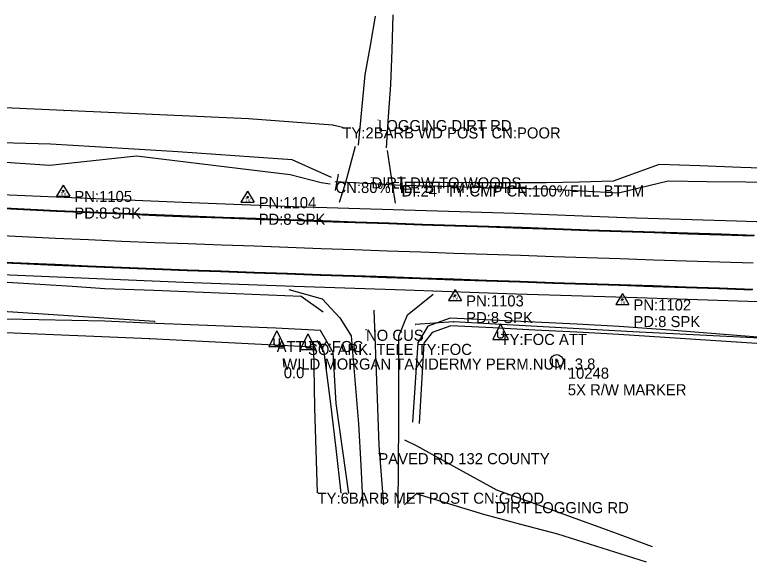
# Model space of a CAD drawing. Extents: x 878399 to 889864, y 1564003 to 1567413.
# Drawn here: x 887107.2 to 887438.5, y 1564312.3 to 1564559.3 of the extents above; entities that cross this region are included whole.
import ezdxf

# ---------------------------------------------------------------- set-up
doc = ezdxf.new("R2010")
doc.units = 0
for name, color, linetype in [('S_DITCHLINE', 7, 'Continuous'), ('S_DRG_PT_SYM', 7, 'Continuous'), ('S_DRIVEWAY', 7, 'Continuous'), ('S_EDGE_PAVEMENT', 7, 'Continuous'), ('S_FENCE', 7, 'Continuous'), ('S_FENCE_ANNOT', 7, 'Continuous'), ('S_FIBER_OPTIC_CABLE', 7, 'Continuous'), ('S_HEADWALL', 7, 'Continuous'), ('S_IRON_PIN', 7, 'Continuous'), ('S_IRON_PIN_ANNOT', 7, 'Continuous'), ('S_MSC_PT_SYM', 7, 'Continuous'), ('S_PAVEMENT_CROWN', 7, 'Continuous'), ('S_SECONDARY_CTL', 7, 'Continuous'), ('S_SECONDARY_CTL_ANNOT', 7, 'Continuous'), ('S_SHOULDER', 7, 'Continuous'), ('S_SIDE_DRAIN', 7, 'Continuous'), ('S_SIDE_DRAIN_ANNOT', 7, 'Continuous'), ('S_SIGN', 7, 'Continuous'), ('S_SIGN_ANNOT', 7, 'Continuous'), ('S_SURVEY_TEXT_ANNOT', 7, 'Continuous'), ('S_TRAILS', 7, 'Continuous'), ('S_UTILITY_POLE', 7, 'Continuous'), ('S_UTILITY_POLE_ANNOT', 7, 'Continuous'), ('S_UTL_PT_SYM', 7, 'Continuous')]:
    doc.layers.add(name, color=color, linetype=linetype)

msp = doc.modelspace()

# ---------------------------------------------------------------- linework, layer by layer
at = {"layer": 'S_DITCHLINE'}
for points in [[(887250.01, 1564485.81), (887245.73, 1564487.85), (887232.27, 1564493.81), (887215.08, 1564494.99), (887197.9, 1564496.18), (887180.71, 1564497.37), (887163.52, 1564498.56), (887143.39, 1564499.75), (887123.26, 1564500.95), (887100.99, 1564501.53), (887078.71, 1564502.11), (887056.44, 1564502.7), (887034.17, 1564503.28), (887025.82, 1564506), (887012.29, 1564506.57), (886998.76, 1564507.13), (886985.23, 1564507.7), (886971.7, 1564508.27), (886951.72, 1564511), (886939.09, 1564511.66), (886934.32, 1564513.76), (886930.08, 1564521.74), (886921.5, 1564529.82)], [(887249.48, 1564482.84), (887245.32, 1564483.43), (887231.36, 1564487.02), (887214.02, 1564489.13), (887196.69, 1564491.24), (887179.36, 1564493.35), (887162.02, 1564495.47), (887142.5, 1564493.34), (887122.97, 1564491.22), (887100.76, 1564492.83), (887078.55, 1564494.43), (887056.34, 1564496.04), (887034.13, 1564497.65), (887018.27, 1564499.44), (887002.4, 1564501.24), (886986.53, 1564503.03), (886970.67, 1564504.83), (886951.34, 1564504.75), (886940.46, 1564504.61), (886937.16, 1564502.38), (886934.26, 1564496.23)], [(887453.1, 1564489.78), (887434.65, 1564490.42), (887416.2, 1564491.05), (887397.75, 1564491.69), (887377.12, 1564484.24), (887361.95, 1564483.82), (887346.78, 1564483.41), (887330.86, 1564483.46), (887314.93, 1564483.51), (887299, 1564483.57), (887283.07, 1564483.62)], [(887454.31, 1564483.52), (887436.85, 1564483.75), (887419.4, 1564483.97), (887401.94, 1564484.19), (887379.4, 1564478.72), (887363.07, 1564479.63), (887346.74, 1564480.55), (887330.76, 1564480.96), (887314.77, 1564481.37), (887298.78, 1564481.79), (887282.79, 1564482.2)], [(887257.8, 1564343.38), (887254.99, 1564363.66), (887252.17, 1564383.94), (887250.75, 1564406.9), (887245.07, 1564416.93), (887224.89, 1564417.88), (887205.62, 1564418.66), (887186.36, 1564419.45), (887167.1, 1564420.23), (887147.83, 1564421.01), (887132.93, 1564421.35), (887118.03, 1564421.7), (887103.12, 1564422.04), (887088.22, 1564422.38), (887066.16, 1564423.4), (887044.11, 1564424.42), (887022.06, 1564425.44), (887000, 1564426.46), (886983.96, 1564429.17), (886968.92, 1564431.25), (886953.89, 1564433.34), (886937.25, 1564432.42), (886929.06, 1564437.68), (886932.3, 1564446.5)], [(887442.27, 1564413.89), (887421.45, 1564415.51), (887400.62, 1564417.12), (887379.8, 1564418.74), (887360.74, 1564419.67), (887341.68, 1564420.6), (887322.62, 1564421.53), (887303.56, 1564422.46), (887293.42, 1564418.88), (887288.97, 1564411.32), (887287.77, 1564393.41), (887286.57, 1564375.5)], [(887441.87, 1564411.02), (887421.14, 1564412.39), (887400.4, 1564413.76), (887379.67, 1564415.13), (887360.72, 1564416.1), (887341.77, 1564417.08), (887322.82, 1564418.05), (887303.87, 1564419.02), (887295.37, 1564416), (887291.62, 1564411.11), (887290.63, 1564393.01), (887289.64, 1564374.92)], [(887254.42, 1564343.43), (887252.11, 1564363.6), (887249.8, 1564383.77), (887246.75, 1564407.12), (887243.59, 1564412.39)]]:
    msp.add_lwpolyline(points, dxfattribs=at)
at = {"layer": 'S_DRG_PT_SYM'}
for points in [[(887251.84, 1564483.86), (887251.84, 1564483.91), (887251.84, 1564483.86), (887251.79, 1564483.86), (887251.84, 1564483.86), (887251.84, 1564483.81), (887251.84, 1564483.86), (887251.89, 1564483.86)], [(887281.64, 1564482.29), (887281.64, 1564482.34), (887281.64, 1564482.29), (887281.59, 1564482.29), (887281.64, 1564482.29), (887281.64, 1564482.24), (887281.64, 1564482.29), (887281.69, 1564482.29)]]:
    msp.add_lwpolyline(points, dxfattribs=at)
at = {"layer": 'S_DRIVEWAY'}
for points in [[(887253.63, 1564474.8), (887256.38, 1564483.18), (887260.84, 1564500)], [(887275.19, 1564498), (887277.41, 1564483.04), (887278.79, 1564474.31)]]:
    msp.add_lwpolyline(points, dxfattribs=at)
at = {"layer": 'S_EDGE_PAVEMENT'}
for points in [[(887096.19, 1564472.17), (887111.17, 1564471.44), (887125.93, 1564470.72), (887125.93, 1564470.72), (887125.93, 1564470.72), (887140.91, 1564470.04), (887155.89, 1564469.42), (887170.87, 1564468.79), (887185.85, 1564468.18), (887200.84, 1564467.65), (887215.82, 1564467.12), (887230.81, 1564466.59), (887245.79, 1564466.07), (887260.77, 1564465.56), (887275.76, 1564465.05), (887290.75, 1564464.55), (887305.73, 1564464.06), (887320.72, 1564463.57), (887335.7, 1564463.07), (887350.68, 1564462.53), (887365.65, 1564461.99), (887380.63, 1564461.45), (887395.62, 1564460.99), (887410.61, 1564460.53), (887425.59, 1564460.07), (887440.58, 1564459.57)], [(887096.49, 1564472.5), (887111.46, 1564471.77), (887126.23, 1564471.05), (887126.23, 1564471.05), (887126.23, 1564471.05), (887141.21, 1564470.38), (887156.18, 1564469.75), (887171.16, 1564469.12), (887186.15, 1564468.51), (887201.13, 1564467.98), (887216.11, 1564467.45), (887231.1, 1564466.92), (887246.08, 1564466.41), (887261.06, 1564465.9), (887276.05, 1564465.38), (887291.03, 1564464.88), (887306.02, 1564464.39), (887321, 1564463.9), (887335.98, 1564463.4), (887350.97, 1564462.86), (887365.93, 1564462.33), (887380.91, 1564461.79), (887395.9, 1564461.32), (887410.89, 1564460.86), (887425.87, 1564460.41), (887440.86, 1564459.9)], [(887094.8, 1564447.72), (887109.78, 1564447.06), (887125.06, 1564446.4), (887140.04, 1564445.76), (887155.02, 1564445.15), (887170, 1564444.53), (887184.98, 1564443.93), (887199.96, 1564443.4), (887214.95, 1564442.87), (887229.93, 1564442.35), (887244.92, 1564441.83), (887259.9, 1564441.33), (887274.89, 1564440.82), (887289.88, 1564440.3), (887304.86, 1564439.78), (887319.84, 1564439.26), (887334.83, 1564438.74), (887334.83, 1564438.74), (887349.81, 1564438.25), (887364.82, 1564437.76), (887379.81, 1564437.27), (887394.79, 1564436.76), (887409.78, 1564436.24), (887424.76, 1564435.73), (887439.75, 1564435.22)], [(887095.09, 1564448.05), (887110.08, 1564447.4), (887125.35, 1564446.73), (887140.33, 1564446.09), (887155.31, 1564445.48), (887170.29, 1564444.87), (887185.27, 1564444.26), (887200.26, 1564443.74), (887215.24, 1564443.21), (887230.22, 1564442.68), (887245.21, 1564442.17), (887260.19, 1564441.66), (887275.18, 1564441.15), (887290.16, 1564440.64), (887305.15, 1564440.11), (887320.13, 1564439.59), (887335.11, 1564439.07), (887335.11, 1564439.07), (887350.1, 1564438.58), (887365.11, 1564438.09), (887380.09, 1564437.61), (887395.07, 1564437.1), (887410.06, 1564436.58), (887425.04, 1564436.06), (887440.03, 1564435.55)], [(887230.77, 1564435.39), (887245.83, 1564431.09), (887253.86, 1564422.63), (887258.88, 1564414.4), (887260.57, 1564394.56), (887262.25, 1564374.72), (887263.24, 1564356.07), (887264.22, 1564337.43)], [(887230.77, 1564435.39), (887245.83, 1564431.09), (887253.86, 1564422.63), (887258.88, 1564414.4), (887260.57, 1564394.56), (887262.25, 1564374.72), (887263.24, 1564356.07), (887264.22, 1564337.43)], [(887280.03, 1564336.91), (887280.19, 1564356.21), (887280.35, 1564375.52), (887280.41, 1564394.91), (887280.46, 1564414.31), (887284.37, 1564423.97), (887295.84, 1564433.31)], [(887280.03, 1564336.91), (887280.19, 1564356.21), (887280.35, 1564375.52), (887280.41, 1564394.91), (887280.46, 1564414.31), (887284.37, 1564423.97), (887295.84, 1564433.31)]]:
    msp.add_lwpolyline(points, dxfattribs=at)
at = {"layer": 'S_FENCE'}
for p, q in [((887129.36, 1564516.14), (887041.56, 1564519.77)), ((887212.6, 1564512.39), (887129.36, 1564516.14)), ((887250.71, 1564509.45), (887212.6, 1564512.39)), ((887254.95, 1564508.47), (887250.71, 1564509.45)), ((887168.04, 1564413.11), (887041.64, 1564418.49)), ((887242.08, 1564409.4), (887168.04, 1564413.11)), ((887242.48, 1564382), (887242.08, 1564409.4)), ((887243.76, 1564343.74), (887242.48, 1564382))]:
    msp.add_line(p, q, dxfattribs=at)
at = {"layer": 'S_FIBER_OPTIC_CABLE'}
for p, q in [((887170.15, 1564420.88), (887088.63, 1564426.34)), ((887304.99, 1564420.78), (887287.85, 1564419.57)), ((887385.92, 1564416.28), (887304.99, 1564420.78)), ((887488.84, 1564411.08), (887385.92, 1564416.28))]:
    msp.add_line(p, q, dxfattribs=at)
at = {"layer": 'S_HEADWALL'}
for points in [[(887251.9, 1564479.95), (887253.17, 1564487.35)], [(887286.41, 1564480.41), (887281.29, 1564480.58), (887281.42, 1564486.25)]]:
    msp.add_lwpolyline(points, dxfattribs=at)
at = {"layer": 'S_IRON_PIN'}
for radius in [2.91, 0.411, 0.262, 0.212, 0.145, 0.0822, 0.0581]:
    msp.add_circle((887351.63, 1564403.12), radius, dxfattribs=at)
at = {"layer": 'S_MSC_PT_SYM'}
for points in [[(887129.36, 1564516.14), (887129.36, 1564516.19), (887129.36, 1564516.14), (887129.31, 1564516.14), (887129.36, 1564516.14), (887129.36, 1564516.09), (887129.36, 1564516.14), (887129.41, 1564516.14)], [(887212.6, 1564512.39), (887212.6, 1564512.44), (887212.6, 1564512.39), (887212.55, 1564512.39), (887212.6, 1564512.39), (887212.6, 1564512.34), (887212.6, 1564512.39), (887212.65, 1564512.39)], [(887250.71, 1564509.45), (887250.71, 1564509.5), (887250.71, 1564509.45), (887250.66, 1564509.45), (887250.71, 1564509.45), (887250.71, 1564509.4), (887250.71, 1564509.45), (887250.76, 1564509.45)], [(887271.07, 1564511.77), (887271.07, 1564511.82), (887271.07, 1564511.77), (887271.02, 1564511.77), (887271.07, 1564511.77), (887271.07, 1564511.72), (887271.07, 1564511.77), (887271.12, 1564511.77)], [(887254.95, 1564508.47), (887254.95, 1564508.52), (887254.95, 1564508.47), (887254.9, 1564508.47), (887254.95, 1564508.47), (887254.95, 1564508.42), (887254.95, 1564508.47), (887255, 1564508.47)], [(887268.08, 1564485.92), (887268.08, 1564485.97), (887268.08, 1564485.92), (887268.03, 1564485.92), (887268.08, 1564485.92), (887268.08, 1564485.87), (887268.08, 1564485.92), (887268.13, 1564485.92)], [(887265.6, 1564417.2), (887265.6, 1564417.25), (887265.6, 1564417.2), (887265.55, 1564417.2), (887265.6, 1564417.2), (887265.6, 1564417.15), (887265.6, 1564417.2), (887265.65, 1564417.2)], [(887168.04, 1564413.11), (887168.04, 1564413.16), (887168.04, 1564413.11), (887167.99, 1564413.11), (887168.04, 1564413.11), (887168.04, 1564413.06), (887168.04, 1564413.11), (887168.09, 1564413.11)], [(887242.08, 1564409.4), (887242.08, 1564409.45), (887242.08, 1564409.4), (887242.03, 1564409.4), (887242.08, 1564409.4), (887242.08, 1564409.35), (887242.08, 1564409.4), (887242.13, 1564409.4)], [(887228.26, 1564404.23), (887228.26, 1564404.28), (887228.26, 1564404.23), (887228.21, 1564404.23), (887228.26, 1564404.23), (887228.26, 1564404.18), (887228.26, 1564404.23), (887228.31, 1564404.23)], [(887228.52, 1564400.33), (887228.52, 1564400.38), (887228.52, 1564400.33), (887228.47, 1564400.33), (887228.52, 1564400.33), (887228.52, 1564400.28), (887228.52, 1564400.33), (887228.57, 1564400.33)], [(887242.48, 1564382), (887242.48, 1564382.05), (887242.48, 1564382), (887242.43, 1564382), (887242.48, 1564382), (887242.48, 1564381.95), (887242.48, 1564382), (887242.53, 1564382)], [(887271.16, 1564361.56), (887271.16, 1564361.61), (887271.16, 1564361.56), (887271.11, 1564361.56), (887271.16, 1564361.56), (887271.16, 1564361.51), (887271.16, 1564361.56), (887271.21, 1564361.56)], [(887243.76, 1564343.74), (887243.76, 1564343.79), (887243.76, 1564343.74), (887243.71, 1564343.74), (887243.76, 1564343.74), (887243.76, 1564343.69), (887243.76, 1564343.74), (887243.81, 1564343.74)], [(887323.94, 1564339.46), (887323.94, 1564339.51), (887323.94, 1564339.46), (887323.89, 1564339.46), (887323.94, 1564339.46), (887323.94, 1564339.41), (887323.94, 1564339.46), (887323.99, 1564339.46)]]:
    msp.add_lwpolyline(points, dxfattribs=at)
at = {"layer": 'S_PAVEMENT_CROWN'}
for points in [[(887095.49, 1564459.96), (887110.47, 1564459.21), (887125.49, 1564458.49), (887140.47, 1564457.85), (887155.44, 1564457.21), (887170.43, 1564456.56), (887185.41, 1564456.03), (887200.39, 1564455.5), (887215.38, 1564454.97), (887230.36, 1564454.44), (887245.35, 1564453.9), (887260.33, 1564453.37), (887275.32, 1564452.84), (887290.3, 1564452.32), (887305.28, 1564451.81), (887320.27, 1564451.29), (887335.25, 1564450.79), (887350.24, 1564450.29), (887365.23, 1564449.78), (887380.21, 1564449.29), (887395.2, 1564448.8), (887410.18, 1564448.31), (887425.17, 1564447.82), (887440.15, 1564447.32)], [(887269.17, 1564426.01), (887269.9, 1564406.12), (887270.63, 1564386.23), (887271.46, 1564365.01), (887272.49, 1564351.66), (887273.52, 1564338.31)]]:
    msp.add_lwpolyline(points, dxfattribs=at)
at = {"layer": 'S_SECONDARY_CTL'}
for p, q in [((887129.07, 1564482.42), (887126.06, 1564477.47)), ((887129.07, 1564482.42), (887132.02, 1564477.47)), ((887212.17, 1564479.64), (887209.16, 1564474.69)), ((887212.17, 1564479.64), (887215.12, 1564474.69)), ((887126.06, 1564477.47), (887132.02, 1564477.47)), ((887209.16, 1564474.69), (887215.12, 1564474.69)), ((887305.75, 1564435.32), (887302.74, 1564430.37)), ((887305.75, 1564435.32), (887308.7, 1564430.37)), ((887381.22, 1564433.5), (887378.21, 1564428.54)), ((887381.22, 1564433.5), (887384.17, 1564428.54)), ((887302.74, 1564430.37), (887308.7, 1564430.37)), ((887378.21, 1564428.54), (887384.17, 1564428.54))]:
    msp.add_line(p, q, dxfattribs=at)
for centre, radius in [((887129.07, 1564479.81), 0.311), ((887129.07, 1564479.81), 0.183), ((887129.07, 1564479.81), 0.103), ((887212.17, 1564477.03), 0.311), ((887212.17, 1564477.03), 0.183), ((887212.17, 1564477.03), 0.103), ((887305.75, 1564432.71), 0.311), ((887305.75, 1564432.71), 0.183), ((887305.75, 1564432.71), 0.103), ((887381.22, 1564430.89), 0.311), ((887381.22, 1564430.89), 0.183), ((887381.22, 1564430.89), 0.103)]:
    msp.add_circle(centre, radius, dxfattribs=at)
at = {"layer": 'S_SHOULDER'}
for points in [[(886439.19, 1564543.9), (886488.35, 1564534.77), (886536.94, 1564526.51), (886586.36, 1564518.81), (886635.93, 1564512.26), (886685.62, 1564506.57), (886734.54, 1564501.74), (886784.34, 1564497.16), (886834.2, 1564493.36), (886883.7, 1564489.95), (886933.63, 1564487.46), (886983.53, 1564484.37), (887033.43, 1564481.47), (887083.36, 1564478.88), (887132.96, 1564476.84), (887182.9, 1564474.75), (887232.84, 1564472.73), (887282.79, 1564471.29), (887332.75, 1564469.72), (887382.66, 1564467.88), (887432.62, 1564466.36), (887482.58, 1564464.72)], [(886434.5, 1564507.62), (886483.69, 1564498.68), (886533.94, 1564490.3), (886583.39, 1564482.88), (886632.96, 1564476.31), (886682.65, 1564470.63), (886733.41, 1564465.04), (886783.26, 1564461.07), (886833.15, 1564457.67), (886883.53, 1564454.57), (886933.43, 1564451.65), (886983.34, 1564448.74), (887033.23, 1564445.65), (887083.15, 1564442.94), (887133.5, 1564440.74), (887183.43, 1564438.72), (887233.38, 1564436.89), (887283.33, 1564435.19), (887333.28, 1564433.45), (887383.27, 1564431.95), (887433.22, 1564430.22), (887483.18, 1564428.56)], [(887246.33, 1564425.09), (887236.36, 1564432.21), (887214.23, 1564433.08), (887192.1, 1564433.96), (887169.96, 1564434.84), (887147.83, 1564435.71), (887133.15, 1564436.63), (887118.47, 1564437.56), (887103.79, 1564438.48)]]:
    msp.add_lwpolyline(points, dxfattribs=at)
at = {"layer": 'S_SIDE_DRAIN'}
msp.add_line((887281.64, 1564482.29), (887251.84, 1564483.86), dxfattribs=at)
at = {"layer": 'S_SIGN'}
msp.add_line((887228.26, 1564404.23), (887228.52, 1564400.33), dxfattribs=at)
at = {"layer": 'S_TRAILS'}
for points in [[(887277.75, 1564559.28), (887277.2, 1564543.48), (887276.66, 1564527.67), (887275.66, 1564513.44), (887274.67, 1564499.21)], [(887269.8, 1564558.66), (887267.44, 1564545.39), (887265.08, 1564532.12), (887263.6, 1564516.31), (887262.11, 1564500.51)], [(887282.97, 1564367.56), (887288.48, 1564364.92), (887306.43, 1564354.97), (887324.38, 1564345.02), (887340.42, 1564339.24), (887356.47, 1564333.45), (887375.59, 1564326.47), (887394.71, 1564319.49)], [(887392.1, 1564312.32), (887372.12, 1564318.67), (887352.13, 1564325.02), (887335.46, 1564329.43), (887318.78, 1564333.84), (887303.47, 1564338.51), (887288.17, 1564343.18), (887282.94, 1564338.31)]]:
    msp.add_lwpolyline(points, dxfattribs=at)
at = {"layer": 'S_UTILITY_POLE'}
for p, q in [((887326.26, 1564419.86), (887322.73, 1564412.77)), ((887326.26, 1564419.86), (887329.74, 1564412.77)), ((887225.32, 1564416.67), (887221.8, 1564409.58)), ((887225.32, 1564416.67), (887228.81, 1564409.58)), ((887325.05, 1564414.01), (887325.05, 1564416.45)), ((887327.42, 1564416.45), (887327.42, 1564414.01)), ((887224.12, 1564410.82), (887224.12, 1564413.26)), ((887226.48, 1564413.26), (887226.48, 1564410.82)), ((887239.44, 1564415.38), (887235.92, 1564408.28)), ((887239.44, 1564415.38), (887242.93, 1564408.28)), ((887325.67, 1564413.35), (887325.05, 1564414.01)), ((887326.88, 1564413.35), (887325.67, 1564413.35)), ((887327.42, 1564414.01), (887326.88, 1564413.35)), ((887224.74, 1564410.16), (887224.12, 1564410.82)), ((887225.94, 1564410.16), (887224.74, 1564410.16)), ((887226.48, 1564410.82), (887225.94, 1564410.16)), ((887238.24, 1564409.52), (887238.24, 1564411.97)), ((887240.61, 1564411.97), (887240.61, 1564409.52)), ((887322.73, 1564412.77), (887329.74, 1564412.77)), ((887221.8, 1564409.58), (887228.81, 1564409.58)), ((887235.92, 1564408.28), (887242.93, 1564408.28)), ((887238.86, 1564408.87), (887238.24, 1564409.52)), ((887240.06, 1564408.87), (887238.86, 1564408.87)), ((887240.61, 1564409.52), (887240.06, 1564408.87))]:
    msp.add_line(p, q, dxfattribs=at)
at = {"layer": 'S_UTL_PT_SYM'}
for points in [[(887170.15, 1564420.88), (887170.15, 1564420.93), (887170.15, 1564420.88), (887170.1, 1564420.88), (887170.15, 1564420.88), (887170.15, 1564420.83), (887170.15, 1564420.88), (887170.2, 1564420.88)], [(887304.99, 1564420.78), (887304.99, 1564420.83), (887304.99, 1564420.78), (887304.94, 1564420.78), (887304.99, 1564420.78), (887304.99, 1564420.73), (887304.99, 1564420.78), (887305.04, 1564420.78)], [(887287.85, 1564419.57), (887287.85, 1564419.62), (887287.85, 1564419.57), (887287.8, 1564419.57), (887287.85, 1564419.57), (887287.85, 1564419.52), (887287.85, 1564419.57), (887287.9, 1564419.57)], [(887385.92, 1564416.28), (887385.92, 1564416.33), (887385.92, 1564416.28), (887385.87, 1564416.28), (887385.92, 1564416.28), (887385.92, 1564416.23), (887385.92, 1564416.28), (887385.97, 1564416.28)]]:
    msp.add_lwpolyline(points, dxfattribs=at)

# ---------------------------------------------------------------- texts
at = {"layer": 'S_FENCE_ANNOT'}
for s, p in [('TY:2BARB WD POST CN:POOR', (887254.95, 1564503.47)), ('TY:6BARB MET POST CN:GOOD', (887243.76, 1564338.74))]:
    msp.add_text(s, height=5, dxfattribs=at).set_placement(p)
at = {"layer": 'S_IRON_PIN_ANNOT'}
for s, p in [('10248', (887356.63, 1564395.12)), ('5X R/W MARKER', (887356.63, 1564387.62))]:
    msp.add_text(s, height=5, dxfattribs=at).set_placement(p)
at = {"layer": 'S_SECONDARY_CTL'}
for p in [(887127.87, 1564477.8), (887210.96, 1564475.02), (887304.55, 1564430.7), (887380.02, 1564428.88)]:
    msp.add_text('TV', height=1.5, rotation=360, dxfattribs=at).set_placement(p)
at = {"layer": 'S_SECONDARY_CTL_ANNOT'}
for s, p in [('PN:1105', (887134.07, 1564474.81)), ('PN:1104', (887217.17, 1564472.03)), ('PD:8 SPK', (887134.07, 1564467.31)), ('PD:8 SPK', (887217.17, 1564464.53)), ('PN:1103', (887310.75, 1564427.71)), ('PN:1102', (887386.22, 1564425.89)), ('PD:8 SPK', (887310.75, 1564420.21)), ('PD:8 SPK', (887386.22, 1564418.39))]:
    msp.add_text(s, height=5, dxfattribs=at).set_placement(p)
at = {"layer": 'S_SIDE_DRAIN_ANNOT'}
for s, p in [('CN:80%FILL BTTM OF PIPE', (887251.84, 1564478.86)), ('DI:24" TY:CMP CN:100%FILL BTTM ', (887281.64, 1564477.29))]:
    msp.add_text(s, height=5, dxfattribs=at).set_placement(p)
at = {"layer": 'S_SIGN_ANNOT'}
for s, p in [('WILD MORGAN TAXIDERMY PERM.NUM. 3.8', (887228.26, 1564399.23)), ('0.0', (887228.52, 1564395.33))]:
    msp.add_text(s, height=5, dxfattribs=at).set_placement(p)
at = {"layer": 'S_SURVEY_TEXT_ANNOT'}
for s, p in [('LOGGING DIRT RD', (887271.07, 1564506.77)), ('DIRT DW TO WOODS', (887268.08, 1564480.92)), ('NO CUS', (887265.6, 1564412.2)), ('PAVED RD 132 COUNTY', (887271.16, 1564356.56)), ('DIRT LOGGING RD', (887323.94, 1564334.46))]:
    msp.add_text(s, height=5, dxfattribs=at).set_placement(p)
at = {"layer": 'S_UTILITY_POLE_ANNOT'}
for s, p in [('TY:FOC ATT', (887326.26, 1564410.33)), ('ATT TY:FOC', (887225.32, 1564407.14)), ('SO. ARK. TELE TY:FOC', (887239.44, 1564405.84))]:
    msp.add_text(s, height=5, dxfattribs=at).set_placement(p)

doc.saveas('drawing.dxf')
